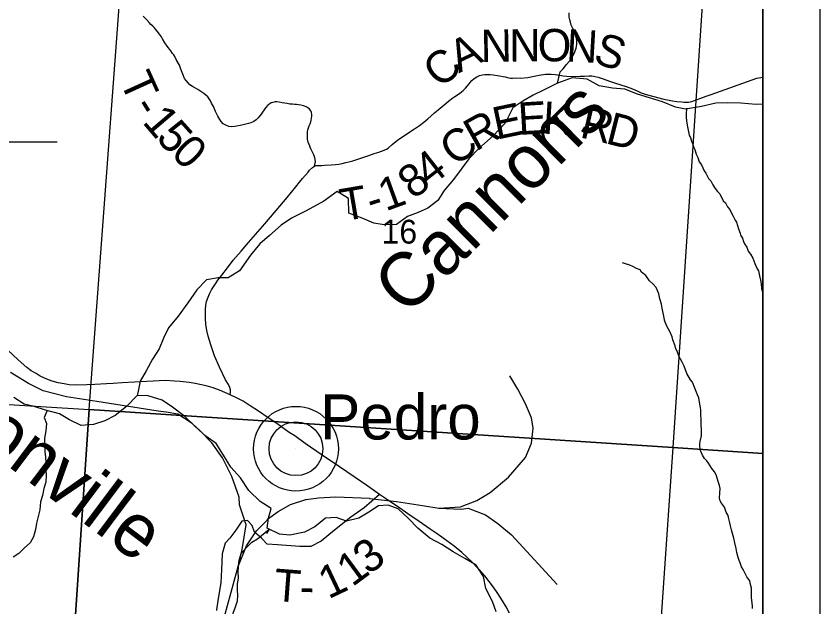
# Model space of a CAD drawing. Extents: x 0 to 82.7, y -0.2 to 22.
# Drawn here: x 7.589 to 9, y 16.831 to 17.868 of the extents above; entities that cross this region are included whole.
import ezdxf

# ---------------------------------------------------------------- set-up
doc = ezdxf.new("R2010")
doc.units = 0
for name, color, linetype in [('GM_X_County_Road', 7, 'Continuous'), ('GM_X_Minor_River', 7, 'Continuous'), ('GM_X_Minor_River_Text', 7, 'Continuous'), ('GM_X_Rail_Line', 7, 'Continuous'), ('GM_X_Section', 7, 'Continuous'), ('GM_X_Section_Text', 7, 'Continuous'), ('GM_X_State_Route', 7, 'Continuous'), ('GM_X_Township_Road', 7, 'Continuous'), ('GM_X_Township_Road_Text', 7, 'Continuous'), ('GM_X_Township_Text', 7, 'Continuous'), ('GM_X_Unincorporated', 7, 'Continuous'), ('GM_X_Unincorporated_Location', 7, 'Continuous'), ('GM_X_Unincorporated_Text', 7, 'Continuous'), ('SH_Cut_Line', 7, 'Continuous'), ('SH_Data', 7, 'Continuous')]:
    doc.layers.add(name, color=color, linetype=linetype)

msp = doc.modelspace()

# ---------------------------------------------------------------- linework, layer by layer
at = {"layer": 'GM_X_County_Road'}
for points in [[(8.9, 17.1004), (8.9, 18.1099), (8.8083, 18.1167), (8.7418, 17.1109)], [(8.9, 16.0927), (8.9, 17.1004), (8.7418, 17.1109), (8.6725, 16.1095)]]:
    msp.add_lwpolyline(points, close=True, dxfattribs=at)
at = {"layer": 'GM_X_Minor_River'}
for points in [[(8.5389, 17.751), (8.5393, 17.7502), (8.5439, 17.7702), (8.5493, 17.7755), (8.5551, 17.783), (8.5597, 17.7886), (8.5635, 17.792), (8.567, 17.7988), (8.5694, 17.8052), (8.5721, 17.812), (8.5729, 17.8181), (8.5734, 17.8249), (8.5727, 17.8287), (8.5709, 17.8356), (8.5694, 17.8402), (8.5661, 17.8467), (8.5635, 17.8524), (8.562, 17.8574), (8.5609, 17.8616), (8.5598, 17.8661), (8.5599, 17.8737)], [(8.6576, 17.7397), (8.6359, 17.7414), (8.6125, 17.746), (8.5913, 17.7575), (8.5648, 17.7596), (8.5393, 17.7502), (8.5146, 17.7382), (8.4963, 17.7296), (8.4784, 17.7186), (8.4609, 17.707), (8.4474, 17.6805), (8.4264, 17.6578), (8.4009, 17.6359), (8.3837, 17.6178), (8.3699, 17.5992), (8.3569, 17.5811), (8.3405, 17.5618), (8.3294, 17.5444), (8.3118, 17.5308), (8.2947, 17.5233), (8.2761, 17.5166), (8.2563, 17.5026), (8.2347, 17.502), (8.2165, 17.5047), (8.1964, 17.5136), (8.1726, 17.522), (8.1724, 17.5479), (8.1524, 17.5601), (8.1291, 17.5432), (8.0979, 17.5266), (8.072, 17.5135), (8.0541, 17.5014), (8.0335, 17.4829), (8.0164, 17.4682), (8.0003, 17.4485), (7.9812, 17.4209), (7.961, 17.4089), (7.9432, 17.409), (7.923, 17.4053), (7.9062, 17.3879), (7.8902, 17.3648), (7.8733, 17.3414), (7.8565, 17.3209), (7.8477, 17.3028), (7.8396, 17.2838), (7.8281, 17.266), (7.8173, 17.2456), (7.8066, 17.2274), (7.8023, 17.2069), (7.8015, 17.202)], [(8.9, 17.7137), (8.8883, 17.7131), (8.8614, 17.7155), (8.8379, 17.716), (8.8174, 17.7153), (8.792, 17.7094), (8.7639, 17.705), (8.7465, 17.7085), (8.7238, 17.7174), (8.7007, 17.7247), (8.6799, 17.7309), (8.6576, 17.7397)], [(8.7655, 17.7066), (8.765, 17.6963), (8.7649, 17.691), (8.7656, 17.6842), (8.7671, 17.6769), (8.7707, 17.6594), (8.7729, 17.6552), (8.7743, 17.6487), (8.7765, 17.6445), (8.7784, 17.6377), (8.7806, 17.6338), (8.7828, 17.6258), (8.7854, 17.6197), (8.7879, 17.6125), (8.7921, 17.6071), (8.7965, 17.5964), (8.7999, 17.5926), (8.8043, 17.583), (8.8084, 17.5788), (8.8121, 17.5719), (8.8162, 17.5658), (8.82, 17.5604), (8.8241, 17.5562), (8.8304, 17.5439), (8.8345, 17.5404), (8.8379, 17.5332), (8.8416, 17.5286), (8.8442, 17.5236), (8.8479, 17.5171), (8.8513, 17.5102), (8.8535, 17.5064), (8.8571, 17.4949), (8.8601, 17.4873), (8.8604, 17.4835), (8.8638, 17.4785), (8.866, 17.4724), (8.8678, 17.4686), (8.8716, 17.4628), (8.8741, 17.4556), (8.8779, 17.4502), (8.8823, 17.4433), (8.886, 17.4338), (8.8901, 17.4246), (8.892, 17.4208), (8.8938, 17.4124), (8.8956, 17.4044), (8.8966, 17.3983), (8.8977, 17.3899), (8.8984, 17.3861), (8.8995, 17.3808), (8.9, 17.3789)], [(8.8817, 16.8282), (8.8814, 16.8324), (8.8803, 16.8427), (8.88, 16.8469), (8.8797, 16.851), (8.8798, 16.864), (8.8784, 16.8701), (8.8769, 16.8765), (8.8717, 16.8838), (8.868, 16.8911), (8.865, 16.8964), (8.8621, 16.9014), (8.8599, 16.9083), (8.858, 16.9125), (8.8562, 16.9178), (8.8544, 16.9266), (8.8529, 16.9335), (8.8504, 16.9434), (8.849, 16.9517), (8.8464, 16.9601), (8.845, 16.9666), (8.8432, 16.9735), (8.8417, 16.9788), (8.8403, 16.9857), (8.8388, 16.9914), (8.8355, 16.9975), (8.8325, 17.0059), (8.8269, 17.0132), (8.8247, 17.0174), (8.8236, 17.022), (8.8245, 17.0311), (8.8246, 17.0391), (8.8235, 17.044), (8.822, 17.0497), (8.8176, 17.0631), (8.8147, 17.0684), (8.8102, 17.0738), (8.8046, 17.0834), (8.8016, 17.0872), (8.7975, 17.0918), (8.7941, 17.0972), (8.7901, 17.1056), (8.789, 17.1128), (8.7894, 17.1178), (8.7899, 17.1216), (8.7919, 17.1314), (8.792, 17.139), (8.792, 17.1432), (8.7917, 17.1497), (8.7914, 17.1573), (8.7915, 17.1611), (8.7911, 17.1668), (8.7909, 17.1766), (8.7905, 17.1808), (8.7891, 17.1869), (8.7873, 17.198), (8.7851, 17.2033), (8.7803, 17.2148), (8.7763, 17.2255), (8.7725, 17.2297), (8.7666, 17.2408), (8.7618, 17.2534), (8.7577, 17.2618), (8.7529, 17.2698), (8.7496, 17.2797), (8.7466, 17.2855), (8.7459, 17.2893), (8.7415, 17.2996), (8.7408, 17.3049), (8.7367, 17.3145), (8.7319, 17.3225), (8.7285, 17.3306), (8.7274, 17.3344), (8.7264, 17.3386), (8.7231, 17.3557), (8.7217, 17.3622), (8.7192, 17.3721), (8.717, 17.3805), (8.7126, 17.3919), (8.7073, 17.3977), (8.7009, 17.4035), (8.6946, 17.4127), (8.6867, 17.4188), (8.6841, 17.4227), (8.678, 17.425), (8.6716, 17.4289), (8.666, 17.4309), (8.6569, 17.4337), (8.6531, 17.4352)], [(8.4315, 16.8221), (8.4251, 16.8403), (8.4135, 16.8635), (8.4095, 16.8841), (8.3964, 16.9043), (8.3767, 16.9161), (8.3563, 16.9276), (8.3359, 16.9403), (8.3152, 16.9518), (8.294, 16.969), (8.2775, 16.9865), (8.2594, 17.0029), (8.242, 17.0099), (8.2249, 17.0084), (8.2078, 16.9975), (8.1902, 16.987), (8.169, 16.9814), (8.1504, 16.9879), (8.1318, 16.9869), (8.1132, 16.9718), (8.0953, 16.9624), (8.0691, 16.9568), (8.0509, 16.9585), (8.0297, 16.9692), (8.0321, 16.9867), (8.0368, 17.0037), (8.0171, 17.016), (7.9972, 17.0354), (7.9825, 17.0575), (7.9656, 17.0762), (7.9528, 17.0972), (7.9397, 17.1178), (7.9216, 17.1308), (7.9031, 17.1479), (7.885, 17.1651), (7.8631, 17.1816), (7.8454, 17.1942), (7.8204, 17.2015), (7.8015, 17.202), (7.7824, 17.1831), (7.7629, 17.1673), (7.7443, 17.1579), (7.7245, 17.1515), (7.7029, 17.1494), (7.6825, 17.1593), (7.6651, 17.1697), (7.6405, 17.1766), (7.6205, 17.1828), (7.6027, 17.1871), (7.5845, 17.1989)], [(7.6435, 17.1758), (7.6377, 17.1636), (7.6418, 17.1529), (7.6409, 17.14), (7.6386, 17.1272), (7.6385, 17.1158), (7.6392, 17.104), (7.6402, 17.0941), (7.6409, 17.0846), (7.6408, 17.0721), (7.6415, 17.0619), (7.6407, 17.0501), (7.6372, 17.0388), (7.6348, 17.0266), (7.6317, 17.0153), (7.6305, 17.0016), (7.6274, 16.9899), (7.6247, 16.9781), (7.6227, 16.9668), (7.6192, 16.9543), (7.6134, 16.9433), (7.6035, 16.935), (7.5936, 16.9245), (7.5837, 16.9181)], [(7.9308, 16.7373), (7.9558, 16.779), (7.9631, 16.7903), (7.9654, 16.7998), (7.9678, 16.8096), (7.9697, 16.8199), (7.9736, 16.8312), (7.9774, 16.8414), (7.9779, 16.8509), (7.9772, 16.8612), (7.9773, 16.871), (7.9789, 16.882), (7.9785, 16.8919), (7.979, 16.9021), (7.9806, 16.9131), (7.9837, 16.9245), (7.9932, 16.9354), (8.0028, 16.9445), (8.0123, 16.9508), (8.0331, 16.9675), (8.0286, 16.9598)]]:
    msp.add_lwpolyline(points, dxfattribs=at)
at = {"layer": 'GM_X_Rail_Line'}
for points in [[(7.9788, 16.902), (7.9855, 16.9316), (7.9926, 16.9749), (7.9807, 17.0103), (7.9803, 17.0236), (7.9674, 17.0598), (7.9512, 17.0928), (7.9322, 17.1191), (7.9121, 17.1401), (7.8978, 17.1527), (7.8729, 17.1696), (7.8524, 17.1726), (7.838, 17.1747), (7.7303, 17.1917), (7.6772, 17.1997), (7.6362, 17.2102), (7.6107, 17.2233), (7.5791, 17.2424)], [(8.3311, 17.0042), (8.3689, 17.0066), (8.3979, 17.0179), (8.4212, 17.0316), (8.4534, 17.0589), (8.4832, 17.0935), (8.4936, 17.1185), (8.4968, 17.145), (8.4936, 17.1627), (8.4832, 17.1877), (8.4695, 17.2134), (8.4558, 17.2368)], [(7.9788, 16.902), (7.9933, 16.9382), (7.9941, 16.9398), (8.011, 16.9648), (8.0303, 16.9841), (8.0303, 16.9849), (8.0488, 16.9986), (8.0705, 17.0107), (8.0971, 17.0195), (8.0979, 17.0195), (8.1196, 17.0227), (8.1502, 17.0243), (8.2089, 17.0219), (8.2089, 17.0211), (8.2563, 17.0163), (8.3022, 17.009), (8.3311, 17.0042)], [(8.3311, 17.0042), (8.3702, 17.0028), (8.3823, 17.0046), (8.4129, 16.9925), (8.4345, 16.9776), (8.4583, 16.9575), (8.5386, 16.8703)], [(7.9531, 16.8079), (7.9732, 16.8827), (7.9788, 16.902)]]:
    msp.add_lwpolyline(points, dxfattribs=at)
at = {"layer": 'GM_X_Section'}
for points in [[(7.7927, 18.1915), (8.8083, 18.1167), (8.7418, 17.1109), (7.7171, 17.1775)], [(7.7171, 17.1775), (8.7418, 17.1109), (8.6725, 16.1095), (7.6497, 16.1665)]]:
    msp.add_lwpolyline(points, close=True, dxfattribs=at)
msp.add_lwpolyline([(6.7452, 17.2376), (7.7171, 17.1775), (7.6497, 16.1665), (6.6409, 16.2254), (6.6789, 16.7875)], dxfattribs=at)
at = {"layer": 'GM_X_State_Route'}
for points in [[(8.2267, 17.0286), (8.2061, 17.043), (8.182, 17.0592), (8.1566, 17.0768), (8.1263, 17.0974), (8.0965, 17.118), (8.078, 17.1311), (8.0682, 17.1374), (8.0463, 17.1528), (8.0297, 17.1641), (8.0161, 17.1736), (7.9981, 17.1851), (7.9871, 17.192), (7.9758, 17.1982), (7.9647, 17.2036), (7.9456, 17.2114), (7.9344, 17.2155), (7.9224, 17.219), (7.9113, 17.2215), (7.903, 17.2232), (7.8928, 17.225), (7.8769, 17.2268), (7.8666, 17.2275), (7.8508, 17.2282), (7.818, 17.2265), (7.7748, 17.2242), (7.7589, 17.2232), (7.7472, 17.2226), (7.7271, 17.2212), (7.7131, 17.2206), (7.6939, 17.2204), (7.6819, 17.2211), (7.673, 17.2224), (7.6627, 17.2245), (7.6522, 17.2274), (7.6428, 17.2311), (7.6311, 17.2362), (7.6241, 17.2405), (7.6154, 17.2457), (7.6074, 17.2514), (7.5921, 17.265), (7.5737, 17.2821)], [(8.2581, 17.0071), (8.257, 17.0079), (8.2375, 17.0211), (8.2267, 17.0286)], [(8.4551, 16.8203), (8.4492, 16.8312), (8.4429, 16.8419), (8.4345, 16.8548), (8.4269, 16.8658), (8.4191, 16.8759), (8.4116, 16.8855), (8.4065, 16.8913), (8.4022, 16.896), (8.3969, 16.9014), (8.3913, 16.9076), (8.3795, 16.9191), (8.3711, 16.9267), (8.3578, 16.9375), (8.3451, 16.9469), (8.3361, 16.9533), (8.326, 16.9605), (8.3158, 16.9673), (8.2963, 16.981), (8.2763, 16.9946), (8.2581, 17.0071)]]:
    msp.add_lwpolyline(points, dxfattribs=at)
at = {"layer": 'GM_X_Township_Road'}
msp.add_line((7.37, 17.6479), (7.6608, 17.6474), dxfattribs=at)
for points in [[(8.1128, 17.605), (8.1138, 17.6108), (8.1142, 17.6126), (8.114, 17.6163), (8.1133, 17.6191), (8.1115, 17.6245), (8.1091, 17.6295), (8.106, 17.6353), (8.103, 17.6426), (8.1016, 17.6467), (8.1005, 17.6523), (8.1001, 17.6565), (8.1001, 17.6606), (8.1004, 17.6653), (8.101, 17.6688), (8.1022, 17.6721), (8.1035, 17.6755), (8.1047, 17.6789), (8.1059, 17.6825), (8.1069, 17.6856), (8.1075, 17.6888), (8.108, 17.6927), (8.108, 17.6955), (8.1074, 17.6989), (8.1062, 17.702), (8.1037, 17.705), (8.1004, 17.708), (8.0969, 17.7094), (8.0934, 17.7109), (8.0885, 17.7118), (8.0843, 17.7126), (8.0809, 17.7129), (8.0777, 17.7131), (8.0738, 17.7135), (8.0694, 17.7138), (8.0648, 17.7145), (8.0602, 17.7153), (8.056, 17.7161), (8.0505, 17.7172), (8.0467, 17.7177), (8.0435, 17.7177), (8.0397, 17.7168), (8.0368, 17.716), (8.034, 17.7143), (8.0306, 17.7117), (8.0265, 17.7071), (8.0189, 17.696), (8.0135, 17.6897), (8.0099, 17.6863), (8.0059, 17.6833), (8.0008, 17.681), (7.9969, 17.6797), (7.985, 17.6768), (7.9729, 17.6744), (7.967, 17.6738), (7.9621, 17.6745), (7.9569, 17.6765), (7.9522, 17.6791), (7.9485, 17.683), (7.9463, 17.6864), (7.9427, 17.6927), (7.9386, 17.7008), (7.9351, 17.7093), (7.932, 17.7155), (7.9301, 17.7195), (7.9279, 17.7232), (7.9251, 17.7267), (7.922, 17.7295), (7.918, 17.7325), (7.9131, 17.7357), (7.9078, 17.7394), (7.9034, 17.7417), (7.8982, 17.7448), (7.8939, 17.7478), (7.8905, 17.7512), (7.887, 17.7551), (7.8845, 17.7587), (7.8824, 17.7633), (7.878, 17.7749), (7.8754, 17.7818), (7.87, 17.7923), (7.8674, 17.7974), (7.8655, 17.8002), (7.8635, 17.8024), (7.8606, 17.807), (7.8541, 17.8156), (7.8499, 17.8214), (7.8459, 17.8283), (7.8438, 17.8317), (7.8387, 17.8388), (7.8342, 17.8444), (7.8309, 17.8481), (7.8287, 17.8504), (7.8255, 17.8532), (7.8226, 17.8567), (7.8178, 17.8623), (7.8118, 17.8683)], [(8.1128, 17.605), (8.1153, 17.6057), (8.1189, 17.6061), (8.1202, 17.6062), (8.1252, 17.6062), (8.13, 17.6063), (8.1419, 17.607), (8.1495, 17.6076), (8.1553, 17.6083), (8.1612, 17.6094), (8.1677, 17.6111), (8.1729, 17.6123), (8.1797, 17.6143), (8.1888, 17.6168), (8.2079, 17.6234), (8.2175, 17.6267), (8.2257, 17.6294), (8.2349, 17.6329), (8.2389, 17.6347), (8.242, 17.6362), (8.249, 17.6426), (8.2586, 17.6506), (8.2627, 17.6535), (8.2881, 17.6703), (8.2972, 17.6764), (8.3048, 17.6819), (8.3118, 17.6879), (8.3231, 17.6983), (8.3334, 17.7068), (8.34, 17.7124), (8.3478, 17.7187), (8.3552, 17.7248), (8.359, 17.7268), (8.3674, 17.7325), (8.3708, 17.7352), (8.3734, 17.7374), (8.375, 17.7389), (8.3776, 17.7415), (8.3813, 17.746), (8.384, 17.7493), (8.3861, 17.7519), (8.3889, 17.7553), (8.3928, 17.7586), (8.3979, 17.7617), (8.4025, 17.7638), (8.4074, 17.7653), (8.4116, 17.7658), (8.4212, 17.7657), (8.4265, 17.765), (8.4341, 17.7638), (8.4475, 17.7613), (8.4536, 17.76), (8.4572, 17.7595), (8.4602, 17.7595), (8.4657, 17.7596), (8.4739, 17.7593), (8.4873, 17.7607), (8.4953, 17.7621), (8.5072, 17.7647), (8.5179, 17.766), (8.5223, 17.7664), (8.5284, 17.7661), (8.5354, 17.7656), (8.5401, 17.765), (8.5494, 17.7633), (8.5559, 17.7627), (8.57, 17.7622), (8.5792, 17.7625), (8.5868, 17.763), (8.5943, 17.7635), (8.5993, 17.7634), (8.6056, 17.7624), (8.6106, 17.7611), (8.6194, 17.7578), (8.6305, 17.7539), (8.6409, 17.7504), (8.66, 17.7447), (8.6708, 17.7404), (8.6804, 17.7362), (8.6862, 17.7337), (8.6933, 17.7311), (8.7061, 17.7277), (8.7262, 17.7226), (8.7412, 17.7195), (8.749, 17.7183), (8.7575, 17.7174), (8.7609, 17.7171), (8.7669, 17.717), (8.769, 17.7171), (8.7751, 17.7185), (8.8003, 17.7275), (8.809, 17.7306)], [(8.809, 17.7306), (8.8895, 17.7595), (8.9, 17.7608)], [(8.0862, 17.5764), (8.0914, 17.5831), (8.1012, 17.5944), (8.1041, 17.5976), (8.1089, 17.6022), (8.1128, 17.605)], [(7.9647, 17.2036), (7.9654, 17.2084), (7.9652, 17.2119), (7.9641, 17.2161), (7.9615, 17.2215), (7.9563, 17.2299), (7.9456, 17.2517), (7.9373, 17.2715), (7.9303, 17.291), (7.9259, 17.3062), (7.9235, 17.3165), (7.922, 17.3271), (7.9211, 17.3374), (7.921, 17.3455), (7.9212, 17.3532), (7.9218, 17.3606), (7.9232, 17.3672), (7.9257, 17.3749), (7.9283, 17.3809), (7.9316, 17.3874), (7.9355, 17.3931), (7.9398, 17.3997), (7.9428, 17.4044), (7.95, 17.4135), (7.96, 17.4261), (7.97, 17.4396), (7.9837, 17.4557), (7.9966, 17.4709), (8.0253, 17.5038), (8.0516, 17.5346), (8.0644, 17.5497), (8.0798, 17.5683), (8.0862, 17.5764)], [(8.2267, 17.0286), (8.1998, 17.0048), (8.1766, 16.9883), (8.1476, 16.966), (8.1244, 16.9467), (8.106, 16.937), (8.0866, 16.937), (8.0479, 16.9399), (8.0295, 16.9409), (8.0198, 16.9515), (8.0073, 16.9622), (8.0034, 16.9738), (7.9947, 16.9825), (7.985, 16.9815), (7.9743, 16.966), (7.9637, 16.9515), (7.9559, 16.9428), (7.9502, 16.9244), (7.9492, 16.8964), (7.9482, 16.8731), (7.9434, 16.846), (7.9405, 16.8257), (7.9403, 16.8247)]]:
    msp.add_lwpolyline(points, dxfattribs=at)
at = {"layer": 'GM_X_Township_Text'}
msp.add_lwpolyline([(8.9, 14.1), (8.9, 20.1381), (8.3897, 20.1756), (7.9434, 20.2083), (6.9227, 20.2875), (6.7144, 20.301), (6.2809, 20.329), (6.1569, 20.3371), (6.0773, 20.3422), (5.9906, 20.3478), (5.9672, 20.3493), (3.6288, 20.5056)], dxfattribs=at)
at = {"layer": 'GM_X_Unincorporated'}
for radius in [0.0744, 0.0472]:
    msp.add_circle((8.0801, 17.1087), radius, dxfattribs=at)
at = {"layer": 'GM_X_Unincorporated_Location'}
msp.add_line((8.0801, 17.1087), (8.0801, 17.1087), dxfattribs=at)
at = {"layer": 'SH_Cut_Line'}
msp.add_lwpolyline([(8.9, 14.1), (8.9, 20.9), (6.1272, 20.9), (5.9756, 20.3782), (5.9672, 20.3493), (3.6288, 20.5056), (3.179, 20.5374), (2.884, 20.5583), (2.8651, 20.279), (2.8645, 20.2703), (2.8645, 20.2693), (2.8288, 19.7415), (2.7788, 19.0007), (2.7784, 18.9951), (2.7199, 18.1299), (3.0279, 17.3486), (3.0556, 17.2782), (3.2909, 16.7562), (3.4071, 16.476), (3.6125, 15.9807), (3.8036, 15.5496), (4.1209, 14.8338)], dxfattribs=at)
at = {"layer": 'SH_Data'}
for p, q in [((9, 21), (9, 14)), ((8.9, 20.9), (8.9, 14.1))]:
    msp.add_line(p, q, dxfattribs=at)

# ---------------------------------------------------------------- texts
at = {"layer": 'GM_X_Minor_River_Text'}
for s, height, rotation, p in [('Cannons', 0.09469, 44.7238, (8.2748, 17.3394)), ('Ellisonville', 0.094688, 323.0648, (7.33, 17.2613))]:
    msp.add_text(s, height=height, rotation=rotation, dxfattribs=at).set_placement(p)
at = {"layer": 'GM_X_Section_Text'}
msp.add_text('16', height=0.04186, rotation=0, dxfattribs=at).set_placement((8.2305, 17.4688))
at = {"layer": 'GM_X_Township_Road_Text'}
for s, rotation, p in [('N', 0.98, (8.4048, 17.7876)), ('N', 0.2714, (8.4546, 17.7884)), ('O', 0.2477, (8.5046, 17.7887)), ('N', 356.7618, (8.5537, 17.7889)), ('A', 25.5061, (8.3659, 17.7675)), ('S', 342.4028, (8.5999, 17.7868)), ('C', 39.8031, (8.3332, 17.7397)), ('T', 294.4333, (7.7697, 17.7547)), ('-', 301.9874, (7.7912, 17.7088)), ('E', 11.8218, (8.4321, 17.6511)), ('E', 3.4175, (8.4715, 17.6595)), ('K', 356.4496, (8.5121, 17.6621)), ('1', 310.4588, (7.8089, 17.6817)), ('R', 29.1964, (8.3956, 17.6299)), ('R', 346.8971, (8.5767, 17.6558)), ('D', 345.7464, (8.6218, 17.6453)), ('5', 311.8019, (7.8326, 17.6539)), ('C', 37.8223, (8.3606, 17.6026)), ('0', 315.4946, (7.8587, 17.625)), ('4', 38.0164, (8.3155, 17.5672)), ('8', 36.334, (8.2859, 17.5454)), ('1', 20.0282, (8.2375, 17.5251)), ('T', 9.7195, (8.1627, 17.5078)), ('-', 18.0312, (8.2133, 17.5171)), ('3', 36.9202, (8.2075, 16.8862)), ('1', 36.3832, (8.1788, 16.8651)), ('T', 355.6264, (8.04, 16.8418)), ('1', 25.3151, (8.1369, 16.844)), ('-', 359.3496, (8.0864, 16.8384))]:
    msp.add_text(s, height=0.0568, rotation=rotation, dxfattribs=at).set_placement(p)
at = {"layer": 'GM_X_Unincorporated_Text'}
msp.add_text('Pedro', height=0.07898, rotation=0, dxfattribs=at).set_placement((8.1226, 17.125))

doc.saveas('drawing.dxf')
